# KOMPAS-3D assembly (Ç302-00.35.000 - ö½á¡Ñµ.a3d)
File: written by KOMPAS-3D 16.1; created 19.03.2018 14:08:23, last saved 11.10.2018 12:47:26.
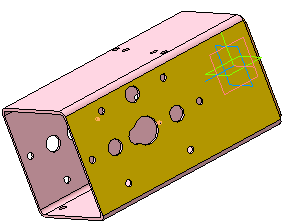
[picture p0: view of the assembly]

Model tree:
1. Эскиз:1
2. Вырезать элемент выдавливания:1
     Расстояние 2 = 265; Расстояние 1 = 4
3. Эскиз:2
4. Вырезать элемент выдавливания:2
     Расстояние 1 = 270
5. Эскиз:3
6. Вырезать элемент выдавливания:3
     Расстояние 1 = 137
7. Эскиз:4
8. Вырезать элемент выдавливания:4
     Расстояние 1 = 269
9. Эскиз:5
10. Вырезать элемент выдавливания:5
     Расстояние 1 = 10
11. Массив по концентрической сетке:1  (with: Вырезать элемент выдавливания:5, Эскиз:5)  (8 pattern instances)
     Геометрический массив = 7; Шаг 2 = 360
12. Эскиз:6
13. Вырезать элемент выдавливания:6
     Расстояние 1 = 139
14. Эскиз:7
15. Вырезать элемент выдавливания:7
     Расстояние 1 = 139
16. Массив по концентрической сетке:2  (with: Вырезать элемент выдавливания:7, Эскиз:7)  (4 pattern instances)
     Геометрический массив = 3; Шаг 2 = 360
17. Эскиз:8
18. Вырезать элемент выдавливания:8
     Расстояние 1 = 139
19. Массив по концентрической сетке:3  (with: Вырезать элемент выдавливания:8, Эскиз:8)  (2 pattern instances)
     Геометрический массив = 1; Шаг 2 = 360
20. Эскиз:9
21. Вырезать элемент выдавливания:9
     Расстояние 1 = 7
22. Зеркальный массив:1
23. Экземпляр ( 1 )
24. Экземпляр ( 2 )  (with: Вырезать элемент выдавливания:9)
25. Эскиз:10
26. Вырезать элемент выдавливания:10
     Расстояние 1 = 139
27. Массив по концентрической сетке:4  (with: Вырезать элемент выдавливания:10, Эскиз:10)  (3 pattern instances)
     Геометрический массив = 2; Шаг 2 = 180
28. Эскиз:11
29. Вырезать элемент выдавливания:11
     Расстояние 1 = 10; На расстояние 1 = 8
30. Зеркальный массив:2  (with: Экземпляр ( 1 ), Экземпляр ( 2 ), Вырезать элемент выдавливания:11)
31. Эскиз:12
32. Вырезать элемент выдавливания:12
     Расстояние 1 = 139; На расстояние 1 = 8
33. Условное изображение резьбы:1  (labels: M4)
     Длина резьбы = 3.5; Шаг резьбы = 0.7; Номинальный диаметр резьбы = 4
34. Подгонка:1
35. Условное изображение резьбы:2  (labels: M4)
     Длина резьбы = 3.5; Шаг резьбы = 0.7; Номинальный диаметр резьбы = 4
36. Подгонка:2
37. Фаска:1
     Угол = 45; Длина 1 = 0.5; Длина 2 = 0.5

Referenced files in Z:\Мембранные насосы\Мембранный электропривод\А302-00.00.000 - ASTRA-302 (МЭ200)\3Д\: А302-00.35.002 - Пластина.m3d, А302-00.35.001 - Труба 140х140х4.m3d
Referenced files in Z:\Мембранные насосы\Мембранный электропривод\А302-00.00.000 - ASTRA-302 (МЭ200)\Чертежи\: А302-00.35.002 - Пластина.cdw, А302-00.35.001 - Труба 140х140х4.cdw
Referenced files: GRAPHIC.TDP
Referenced files in C:\Program Files\ASCON\KOMPAS-3D V16\Sys\Thread\: cil0_8724-2002 coarse.xml
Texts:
  Труба 140х140х4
